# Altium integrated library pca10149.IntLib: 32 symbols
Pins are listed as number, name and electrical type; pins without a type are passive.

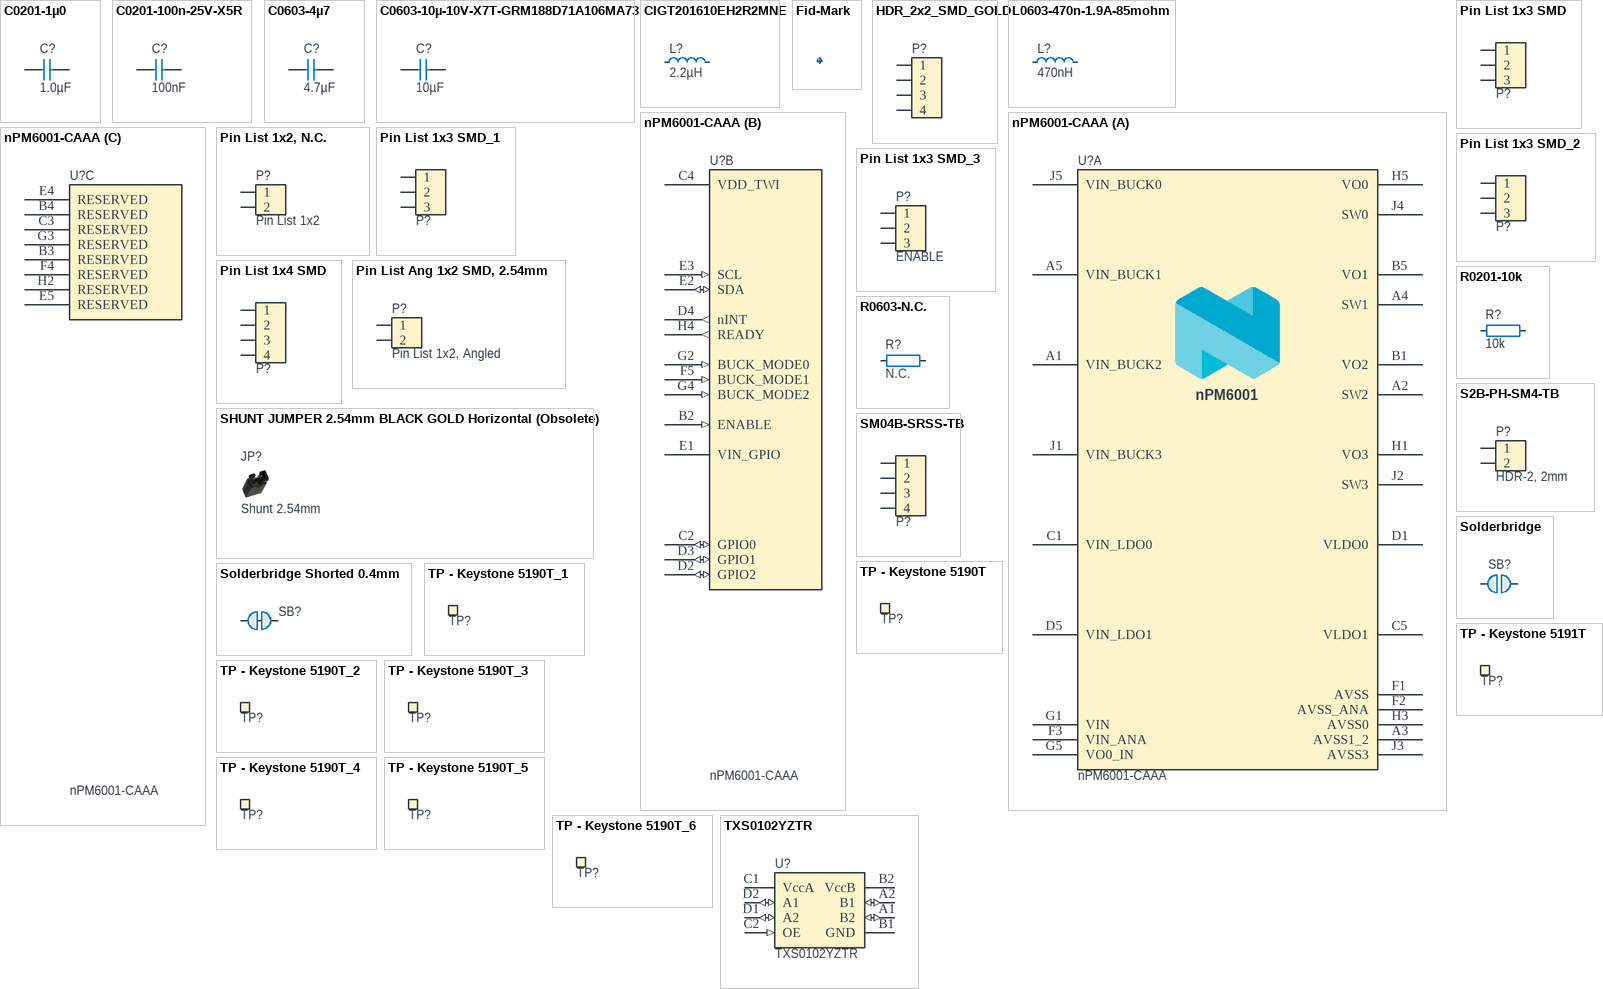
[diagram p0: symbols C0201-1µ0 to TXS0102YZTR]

## C0201-1µ0
designator C?, comment 1.0µF
Capacitor, X5R, ±10%; Part Number: C0201-1µ0; Manufacturer: N.A.; Part number IPS: 00000001723; Pad Count: 2; Note: 10V
footprint CAPC0603X03L_C
pins: 1, 2

## C0201-100n-25V-X5R
designator C?, comment 100nF
Capacitor, Ceramic, X5R, ±10%, 25V; Part Number: C0201-100n-25V-X5R; Manufacturer: Murata; Manufacturer Part Number: GRM033R61E104KE14J; Part number NEMS: 100200459; Pad Count: 2; Artikkelnr Noca: N.A.; Component Status: Active
footprint CAPC0603X03L_C
pins: 1, 2

## C0603-4µ7
designator C?, comment 4.7µF
Capacitor, X5R, ±10%, 6.3V; Part Number: C0603-4µ7; Manufacturer: N.A.; Part number IPS: 00000007783; Part number NEMS: 100200274; Pad Count: 2; Artikkelnr Noca: 20069060; Component Status: Active
footprint CAPC1608X06L
pins: 1, 2

## C0603-10µ-10V-X7T-GRM188D71A106MA73
designator C?, comment 10µF
Capacitor, X7T, ±20%, 10V; Part Number: C0603-10µ-10V-X7T-GRM188D71A106MA73; Manufacturer: Murata; Manufacturer Part Number: GRM188D71A106MA73; Part number IPS: 00000004696; Pad Count: 2; Note: 10VDC; Artikkelnr Noca: N.A.
footprint CAPC1608X06L
pins: 1, 2

## CIGT201610EH2R2MNE
designator L?, comment 2.2µH
FIXED IND 2.2UH 2.5A 87MOHM SMD; Part Number: CIGT201610EH2R2MNE; Manufacturer: Samsung Electro-Mechanics; Part number Norautron: 26521789; Pad Count: 2; Note: 2.2µH Unshielded Thin Film Inductor 2.5A 87mOhm Max 0806 (2016 Metric); Artikkelnr Noca: N.A.
footprint INDC2016X10N
pins: 1, 2

## Fid-Mark
designator Fid?, comment Fiducial mark  (value not drawn)
Part Number: Fid-Mark; Manufacturer: N.A.; Part number NEMS: 100500073; Value: N.A.; Pad Count: 1; Component Status: Active
footprint Fiducial

## HDR_2x2_SMD_GOLD
designator P?, comment Conn 2x2  (value not drawn)
CONN HEADER 4POS .100" VERT 15AU; Part Number: HDR_2x2_SMD_GOLD; Manufacturer: Molex; Part number NEMS: 100500132; Component Status: Active; Pad Count: 4; Note: SMD, gold plating; Artikkelnr Noca: N.A.
footprint HDR_2x2-SMD
pins: 1, 2, 3, 4

## L0603-470n-1.9A-85mohm
designator L?, comment 470nH
FIXED IND 470NH 1.9A 85 MOHM SMD; Part Number: L0603-470n-1.9A-85mohm; Manufacturer: Taiyo Yuden; Manufacturer Part Number: MCFK1608TR47M; Pad Count: 2; Note: -40°C ~ 125°C; Artikkelnr Noca: N.A.
footprint INDC1608X06L
pins: 1, 2

## nPM6001-CAAA
designator U?
Low-power and high efficiency PMIC; Manufacturer: Nordic Semiconductor; Part number NEMS: 102000251; Pad Count: 45; Note: N.A.; Component Status: Active
footprint BGA45C40P5X9_217X364X49
part A pins: A1 VIN_BUCK2 (power), A2 SW2 (power), A3 AVSS1_2 (power), A4 SW1 (power), A5 VIN_BUCK1 (power), B1 VO2 (power), B5 VO1 (power), C1 VIN_LDO0 (power), C5 VLDO1 (power), D1 VLDO0 (power), D5 VIN_LDO1 (power), F1 AVSS (power), F2 AVSS_ANA (power), F3 VIN_ANA (power), G1 VIN (power), G5 VO0_IN (power), H1 VO3 (power), H3 AVSS0 (power), H5 VO0 (power), J1 VIN_BUCK3 (power), J2 SW3 (power), J3 AVSS3 (power), J4 SW0 (power), J5 VIN_BUCK0 (power)
part B pins: B2 ENABLE (in), C2 GPIO0 (io), C4 VDD_TWI (power), D2 GPIO2 (io), D3 GPIO1 (io), D4 nINT (out), E1 VIN_GPIO (power), E2 SDA (io), E3 SCL (in), F5 BUCK_MODE1 (in), G2 BUCK_MODE0 (in), G4 BUCK_MODE2 (in), H4 READY (out)
part C pins: B3 RESERVED, B4 RESERVED, C3 RESERVED, E4 RESERVED, E5 RESERVED, F4 RESERVED, G3 RESERVED, H2 RESERVED

## Pin List 1x2, N.C.
designator P?, comment Pin List 1x2
Pin List 1x2, 2.54mm (100mil); Part Number: Pin List 1x2, N.C.; Manufacturer: N.A.; Part number NEMS: 100500298; Component Status: Active; Pad Count: 2; Assembly: Not mounted
footprint LIST_1x2-NC
pins: 1, 2

## Pin List 1x3 SMD
designator P?, comment BUCK_MODE0  (value not drawn)
Pin List 1x3, 2.54mm (100mil), SMD; Part Number: Pin List 1x3 SMD; Manufacturer: W-CON; Manufacturer Part Number: 1125-1103S0M116CR02; Part number Norautron: 26470016; Part number NEMS: 100500306; Pad Count: 3; Note: N.A.; Component Status: Active
footprint LIST_1x3_SMD
pins: 1, 2, 3

## Pin List 1x3 SMD_1
designator P?, comment BUCK_MODE1  (value not drawn)
Pin List 1x3, 2.54mm (100mil), SMD; Part Number: Pin List 1x3 SMD; Manufacturer: W-CON; Manufacturer Part Number: 1125-1103S0M116CR02; Part number Norautron: 26470016; Part number NEMS: 100500306; Pad Count: 3; Note: N.A.; Component Status: Active
footprint LIST_1x3_SMD
pins: 1, 2, 3

## Pin List 1x3 SMD_2
designator P?, comment BUCK_MODE2  (value not drawn)
Pin List 1x3, 2.54mm (100mil), SMD; Part Number: Pin List 1x3 SMD; Manufacturer: W-CON; Manufacturer Part Number: 1125-1103S0M116CR02; Part number Norautron: 26470016; Part number NEMS: 100500306; Pad Count: 3; Note: N.A.; Component Status: Active
footprint LIST_1x3_SMD
pins: 1, 2, 3

## Pin List 1x3 SMD_3
designator P?, comment ENABLE
Pin List 1x3, 2.54mm (100mil), SMD; Part Number: Pin List 1x3 SMD; Manufacturer: W-CON; Manufacturer Part Number: 1125-1103S0M116CR02; Part number Norautron: 26470016; Part number NEMS: 100500306; Pad Count: 3; Note: N.A.; Component Status: Active
footprint LIST_1x3_SMD
pins: 1, 2, 3

## Pin List 1x4 SMD
designator P?, comment Pin List 1x4  (value not drawn)
Pin List 1x4, 2.54mm (100mil), SMD; Part Number: Pin List 1x4 SMD; Manufacturer: N.A.; Part number NEMS: 100500311; Pad Count: 4; Artikkelnr Noca: 55019234; Component Status: Active
footprint LIST_1x4_SMD
pins: 1, 2, 3, 4

## Pin List Ang 1x2 SMD, 2.54mm
designator P?, comment Pin List 1x2, Angled
Pin List 1x2, 2.54mm (100mil), Right Angled, SMD; Part Number: Pin List Ang 1x2 SMD, 2.54mm; Manufacturer: W-CON; Manufacturer Part Number: 1125B-1102S0Z135R2; Part number IPS: 00000009972; Part number NEMS: 100500354; Pad Count: 2; Note: N.A.; Artikkelnr Noca: 55010023; Component Status: Active
footprint LIST_ANG_1x2-SMD-2.54MM
pins: 1, 2

## R0201-10k
designator R?, comment 10k
Resistor, ±1%, 0.05W; Part Number: R0201-10k; Manufacturer: N.A.; Part number IPS: 00000001255; Part number Norautron: 26107101; Part number NEMS: 100100065; Pad Count: 2; Note: Chip Res 1%; Component Status: Active
footprint RESC0603X03L_C
pins: 1, 2

## R0603-N.C.
designator R?, comment N.C.
Not mounted; Part Number: R0603-N.C.; Manufacturer: N.A.; Part number NEMS: 100100373; Pad Count: 2; Note: Chip Res; Assembly: Not mounted; Component Status: Active
footprint RESC1608X06L_NC
pins: 1, 2

## S2B-PH-SM4-TB
designator P?, comment HDR-2, 2mm
2.0mm pitch connector side entry SMD; Part Number: S2B-PH-SM4-TB; Manufacturer: JST Sales America Inc.; Manufacturer Part Number: S2B-PH-SM4-TB(LF)(SN); Part number NEMS: 100500381; Pad Count: 2; Note: JST, Header; Artikkelnr Noca: N.A.; Component Status: Active
footprint S2B-PH-SM4-TB
pins: 1, 2

## SHUNT JUMPER 2.54mm BLACK GOLD Horizontal (Obsolete)
designator JP?, comment Shunt 2.54mm
Shunt Jumper 2.54mm Black; Part Number: SHUNT JUMPER 2.54mm BLACK GOLD Horizontal (Obsolete); Manufacturer: 3M; Manufacturer Part Number: 969102-0000-DA; Part number IPS: 00000001916; Part number Norautron: N.A.; Part number NEMS: 100500644; Pad Count: 2; Note: SHUNT JUMPER .1" BLACK GOLD, h=6.00mm, w=5.00mm; Artikkelnr Noca: 56099001; Component Status: Obsolete
footprint Shunt_2.54mm_Horizontal

## SM04B-SRSS-TB
designator P?, comment QWIIC  (value not drawn)
JST SR/SH 1.0mm 4-pin; Part Number: SM04B-SRSS-TB; Manufacturer: JST Sales America Inc.; Part number NEMS: 100500540; Pad Count: 4; Value: SM04B-SRSS-TB; Note: N.A.; Component Status: Active
footprint SM04B-SRSS-TB
pins: 1, 2, 3, 4

## Solderbridge
designator SB?  (value not drawn)  (no BOM)
Manufacturer: N.A.; Part number NEMS: 100500458; Pad Count: 2; Component Status: Active
footprint Solderbridge
pins: 1 0, 2 1

## Solderbridge Shorted 0.4mm
designator SB?, comment Solderbridge  (value not drawn)  (net tie, no BOM)
Shorted Solderbridge; Part Number: Solderbridge Shorted 0.4mm; Manufacturer: N.A.; Part number NEMS: 100500561; Pad Count: 2; Component Status: Active
footprint Solderbridge_SHORTED_0.4
pins: 1 0, 2 1

## TP - Keystone 5190T
designator TP?, comment BUCK0  (value not drawn)
Miniature SMT Test Point -Red P/N 5190TR; Part Number: TP - Keystone 5190T; Manufacturer: Keystone; Manufacturer Part Number: 5190T; Part number NEMS: 100500747; Component Status: Active; Pad Count: 1; Value: TP; Note: Keystone 5190TR, RED; Artikkelnr Noca: N.A.
footprint Keystone_5190TR
pins: 1

## TP - Keystone 5190T_1
designator TP?, comment BUCK1  (value not drawn)
Miniature SMT Test Point -Red P/N 5190TR; Part Number: TP - Keystone 5190T; Manufacturer: Keystone; Manufacturer Part Number: 5190T; Part number NEMS: 100500747; Component Status: Active; Pad Count: 1; Value: TP; Note: Keystone 5190TR, RED; Artikkelnr Noca: N.A.
footprint Keystone_5190TR
pins: 1

## TP - Keystone 5190T_2
designator TP?, comment BUCK2  (value not drawn)
Miniature SMT Test Point -Red P/N 5190TR; Part Number: TP - Keystone 5190T; Manufacturer: Keystone; Manufacturer Part Number: 5190T; Part number NEMS: 100500747; Component Status: Active; Pad Count: 1; Value: TP; Note: Keystone 5190TR, RED; Artikkelnr Noca: N.A.
footprint Keystone_5190TR
pins: 1

## TP - Keystone 5190T_3
designator TP?, comment LDO1  (value not drawn)
Miniature SMT Test Point -Red P/N 5190TR; Part Number: TP - Keystone 5190T; Manufacturer: Keystone; Manufacturer Part Number: 5190T; Part number NEMS: 100500747; Component Status: Active; Pad Count: 1; Value: TP; Note: Keystone 5190TR, RED; Artikkelnr Noca: N.A.
footprint Keystone_5190TR
pins: 1

## TP - Keystone 5190T_4
designator TP?, comment LDO0  (value not drawn)
Miniature SMT Test Point -Red P/N 5190TR; Part Number: TP - Keystone 5190T; Manufacturer: Keystone; Manufacturer Part Number: 5190T; Part number NEMS: 100500747; Component Status: Active; Pad Count: 1; Value: TP; Note: Keystone 5190TR, RED; Artikkelnr Noca: N.A.
footprint Keystone_5190TR
pins: 1

## TP - Keystone 5190T_5
designator TP?, comment BUCK3  (value not drawn)
Miniature SMT Test Point -Red P/N 5190TR; Part Number: TP - Keystone 5190T; Manufacturer: Keystone; Manufacturer Part Number: 5190T; Part number NEMS: 100500747; Component Status: Active; Pad Count: 1; Value: TP; Note: Keystone 5190TR, RED; Artikkelnr Noca: N.A.
footprint Keystone_5190TR
pins: 1

## TP - Keystone 5190T_6
designator TP?, comment VIN  (value not drawn)
Miniature SMT Test Point -Red P/N 5190TR; Part Number: TP - Keystone 5190T; Manufacturer: Keystone; Manufacturer Part Number: 5190T; Part number NEMS: 100500747; Component Status: Active; Pad Count: 1; Value: TP; Note: Keystone 5190TR, RED; Artikkelnr Noca: N.A.
footprint Keystone_5190TR
pins: 1

## TP - Keystone 5191T
designator TP?, comment GND  (value not drawn)
Miniature SMT Test Point -Red P/N 5191TR; Part Number: TP - Keystone 5191T; Manufacturer: Keystone; Manufacturer Part Number: 5191T; Part number NEMS: 100500748; Component Status: Active; Pad Count: 1; Value: TP; Note: Keystone 5191TR, BLACK; Artikkelnr Noca: N.A.
footprint Keystone_5191TR
pins: 1

## TXS0102YZTR
designator U?
Voltage Level Translator Bidirectional 1 Circuit 2 Channel 24Mbps 8-DSBGA; Manufacturer: Texas Instruments; Part number NEMS: 101900683; Pad Count: 8; Note: TEXAS INSTRUMENTS - TXS0102YZTR - IC, TRANSLATOR; Artikkelnr Noca: N.A.; Component Status: Active
footprint BGA8C50P2X4_89X189X50
pins: A1 B2 (io) "SDA_B", A2 B1 (io) "SCL_B", B1 GND (power), B2 VccB (power) "B port Vcc", C1 VccA (power) "A port power", C2 OE (in) "Enable (OE) with respect to VccA. Max 4.6V", D1 A2 (io) "SDA_A", D2 A1 (io) "SCL_A"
